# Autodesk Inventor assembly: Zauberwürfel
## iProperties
Created: 2004-10
Part Number: Zauberwürfel
Document SubType Name: Assembly
Designer: sahrens
Manufacturer: Standard
Standards Organization: Custom
Author: sahrens
